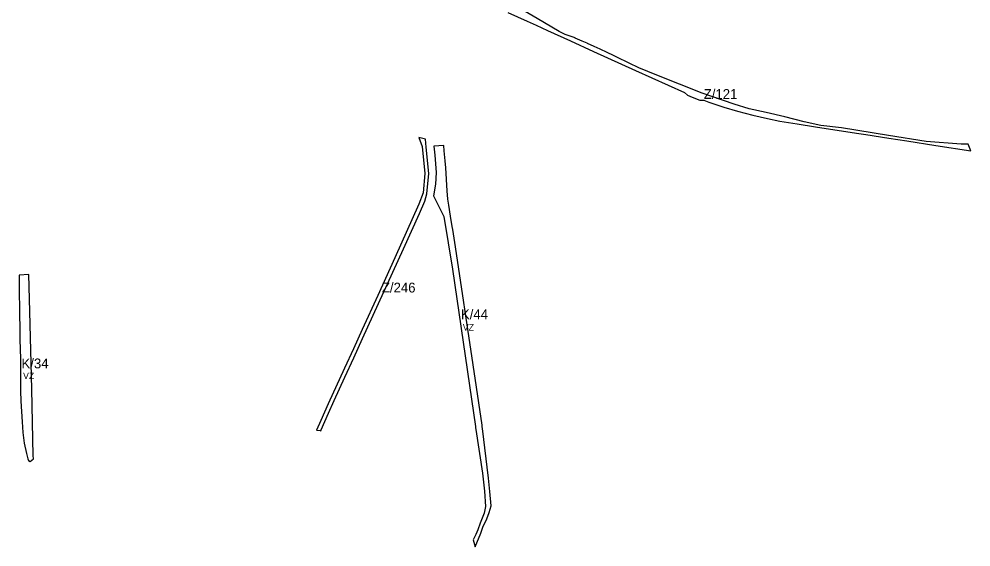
# Model space of a CAD drawing. Extents: x -521939 to -518034, y -1194984 to -1189555.
# Drawn here: x -520595 to -519142, y -1193629 to -1192824 of the extents above; entities that cross this region are included whole.
import ezdxf

# ---------------------------------------------------------------- set-up
doc = ezdxf.new("R2010")
doc.units = 0
for name, color, linetype in [('95420023', 7, 'Continuous'), ('96111023', 7, 'Continuous'), ('96202223', 7, 'Continuous')]:
    doc.layers.add(name, color=color, linetype=linetype)

msp = doc.modelspace()

# ---------------------------------------------------------------- linework, layer by layer
at = {"layer": '95420023'}
for points in [[(-519727.02, -1192861.14), (-519727.74, -1192860.81), (-519735.5, -1192857.45), (-519745.77, -1192853), (-519746.17, -1192852.82), (-519761.29, -1192847.68), (-519770.17, -1192843), (-519803.79, -1192823.02), (-519842.92, -1192800.19)], [(-519848.77, -1192813.79), (-519819.07, -1192827.26)], [(-519819.07, -1192827.26), (-519805.68, -1192833.36)], [(-519805.68, -1192833.36), (-519788.21, -1192841.3)], [(-519788.21, -1192841.3), (-519752.94, -1192857.37)], [(-519752.94, -1192857.37), (-519717.76, -1192873.41)], [(-519717.04, -1192865.69), (-519727.02, -1192861.14)], [(-519717.76, -1192873.41), (-519653.99, -1192902.46)], [(-519707.74, -1192869.98), (-519717.04, -1192865.69)], [(-519677.43, -1192884.57), (-519687.55, -1192879.63), (-519697.18, -1192875), (-519707.74, -1192869.98)], [(-519657.29, -1192894.4), (-519668.57, -1192888.89), (-519677.43, -1192884.57)], [(-519648.88, -1192898.4), (-519655.13, -1192895.45), (-519657.29, -1192894.4)], [(-519653.99, -1192902.46), (-519579.08, -1192936.23)], [(-519621.37, -1192909.57), (-519648.88, -1192898.4)], [(-519551.94, -1192937.22), (-519621.37, -1192909.57)], [(-519579.08, -1192936.23), (-519574.51, -1192940.18), (-519567.2, -1192943.06)], [(-519503.57, -1192953.95), (-519551.94, -1192937.22)], [(-519567.2, -1192943.06), (-519555.74, -1192947.57), (-519549.76, -1192947.78), (-519542.07, -1192950.61)], [(-519542.07, -1192950.61), (-519518.93, -1192958.37)], [(-519518.93, -1192958.37), (-519498.2, -1192964.55)], [(-519480.63, -1192960.73), (-519503.57, -1192953.95)], [(-519498.2, -1192964.55), (-519474.87, -1192970.68)], [(-519425.99, -1192972.98), (-519454.77, -1192966.51), (-519480.63, -1192960.73)], [(-519474.87, -1192970.68), (-519452.37, -1192975.76)], [(-519452.37, -1192975.76), (-519433.72, -1192979.51)], [(-519433.72, -1192979.51), (-519407.22, -1192983.93)], [(-519370.98, -1192986.14), (-519396.52, -1192980.8), (-519425.99, -1192972.98)], [(-519407.22, -1192983.93), (-519379.4, -1192988.21)], [(-519379.4, -1192988.21), (-519316.79, -1192997.86)], [(-519339.75, -1192990.06), (-519370.98, -1192986.14)], [(-519157.21, -1193014.6), (-519210.29, -1193010.83), (-519267.67, -1193001.68), (-519339.75, -1192990.06)], [(-519974.42, -1193007.26), (-519984.44, -1193004.38)], [(-519984.44, -1193004.38), (-519979.35, -1193018.09)], [(-519973.19, -1193019.52), (-519974.42, -1193007.26)], [(-519316.79, -1192997.86), (-519302.57, -1193000.06)], [(-519302.57, -1193000.06), (-519267.23, -1193005.51)], [(-519267.23, -1193005.51), (-519239.74, -1193009.74)], [(-519239.74, -1193009.74), (-519195.48, -1193016.56)], [(-519979.35, -1193018.09), (-519975.45, -1193059.33)], [(-519969.42, -1193059.31), (-519973.19, -1193019.52)], [(-519195.48, -1193016.56), (-519142.04, -1193024.85)], [(-519146.2, -1193014.77), (-519157.21, -1193014.6)], [(-519142.04, -1193024.85), (-519146.2, -1193014.77)], [(-519975.45, -1193059.33), (-519978.09, -1193089.18)], [(-519972.17, -1193090.33), (-519969.42, -1193059.31)], [(-520008.16, -1193174.24), (-519983.64, -1193120.33), (-519975.56, -1193101.44), (-519972.17, -1193090.33)], [(-519978.09, -1193089.18), (-519984.32, -1193106.32)], [(-519984.32, -1193106.32), (-520021.04, -1193188.07)], [(-520070.47, -1193311.24), (-520008.16, -1193174.24)], [(-520021.04, -1193188.07), (-520047.22, -1193245.62)], [(-520047.22, -1193245.62), (-520070.77, -1193297.42)], [(-520070.77, -1193297.42), (-520084.24, -1193326.9)], [(-520083.91, -1193340.59), (-520070.47, -1193311.24)], [(-520084.24, -1193326.9), (-520097.84, -1193356.45)], [(-520097.51, -1193370.06), (-520083.91, -1193340.59)], [(-520097.84, -1193356.45), (-520122.68, -1193410.82)], [(-520122.34, -1193424.94), (-520113.77, -1193405.48), (-520097.51, -1193370.06)], [(-520122.68, -1193410.82), (-520133.9, -1193436.21)], [(-520134.2, -1193451.67), (-520133.56, -1193450.26), (-520122.34, -1193424.94)], [(-520133.9, -1193436.21), (-520140.41, -1193450.83)], [(-520140.41, -1193450.83), (-520134.88, -1193451.49)], [(-520134.88, -1193451.49), (-520134.2, -1193451.67)]]:
    msp.add_lwpolyline(points, dxfattribs=at)
at = {"layer": '96111023'}
for points in [[(-519946.52, -1193016.85), (-519961.59, -1193017.82)], [(-519961.59, -1193017.82), (-519959.95, -1193031.63), (-519957.98, -1193057.97)], [(-519945.63, -1193024.86), (-519946.52, -1193016.85)], [(-519944.11, -1193039.95), (-519945.63, -1193024.86)], [(-519943.25, -1193050.97), (-519944.11, -1193039.95)], [(-519940.04, -1193098.62), (-519941.21, -1193085.76), (-519943.25, -1193050.97)], [(-519957.98, -1193057.97), (-519959.22, -1193075.94)], [(-519959.22, -1193075.94), (-519962.06, -1193093.75)], [(-519962.06, -1193093.75), (-519946.35, -1193125.19), (-519933.38, -1193205.21), (-519907.35, -1193382.83), (-519898.22, -1193445.13)], [(-519938.56, -1193107.97), (-519940.04, -1193098.62)], [(-519936.08, -1193124.31), (-519938.56, -1193107.97)], [(-519933.44, -1193140.29), (-519936.08, -1193124.31)], [(-519932.83, -1193144.89), (-519933.44, -1193140.29)], [(-519928.77, -1193171.13), (-519932.83, -1193144.89)], [(-519887.86, -1193443.3), (-519901.66, -1193351.49), (-519928.77, -1193171.13)], [(-520579.39, -1193213.66), (-520594.54, -1193214.33)], [(-520578.05, -1193270.09), (-520579.39, -1193213.66)], [(-520594.54, -1193214.33), (-520594.36, -1193228.5)], [(-520594.36, -1193228.5), (-520594.2, -1193241.7)], [(-520594.2, -1193241.7), (-520593.91, -1193264.71)], [(-520593.91, -1193264.71), (-520593.84, -1193270.47)], [(-520593.84, -1193270.47), (-520593.48, -1193299.21)], [(-520572.81, -1193489.53), (-520575.23, -1193388.1), (-520578.05, -1193270.09)], [(-520593.48, -1193299.21), (-520593.16, -1193312.67)], [(-520593.16, -1193312.67), (-520592.81, -1193327.52)], [(-520592.81, -1193327.52), (-520592.34, -1193342.18)], [(-520592.34, -1193342.18), (-520592.11, -1193358.68)], [(-520592.11, -1193358.68), (-520592.07, -1193374.76)], [(-520592.07, -1193374.76), (-520592.13, -1193390.79)], [(-520592.13, -1193390.79), (-520591.63, -1193406.88)], [(-520591.63, -1193406.88), (-520590.94, -1193422.65)], [(-520590.94, -1193422.65), (-520590.74, -1193422.65), (-520589.86, -1193438.24)], [(-520589.86, -1193438.24), (-520588.57, -1193454.26)], [(-519897.8, -1193447.56), (-519897.38, -1193449.99), (-519887.36, -1193516.57), (-519884.47, -1193543.82), (-519882.69, -1193567.19), (-519884.76, -1193577.59), (-519890.7, -1193592.62), (-519894.55, -1193602.68), (-519897.73, -1193609.81), (-519901.37, -1193618.32), (-519898.76, -1193628.94), (-519889.94, -1193607.87), (-519886.16, -1193597.43), (-519883.14, -1193591.58), (-519880.89, -1193586.23), (-519877.16, -1193576.19), (-519873.92, -1193566.11), (-519876.28, -1193544.38), (-519878.23, -1193524.18), (-519887.53, -1193448.24), (-519887.69, -1193445.77)], [(-519898.22, -1193445.13), (-519897.8, -1193447.56)], [(-519887.69, -1193445.77), (-519887.86, -1193443.3)], [(-520588.57, -1193454.26), (-520586.93, -1193470.68)], [(-520586.93, -1193470.68), (-520583.19, -1193486.29)], [(-520583.19, -1193486.29), (-520581, -1193494.61)], [(-520572.69, -1193494.62), (-520572.81, -1193489.53)], [(-520581, -1193494.61), (-520580.28, -1193497.37)], [(-520580.28, -1193497.37), (-520577.34, -1193498.47)], [(-520577.34, -1193498.47), (-520572.69, -1193494.62)]]:
    msp.add_lwpolyline(points, dxfattribs=at)
at = {"layer": '96202223'}
for points in [[(-519946.52, -1193016.85), (-519961.59, -1193017.82)], [(-519961.59, -1193017.82), (-519959.95, -1193031.63), (-519957.98, -1193057.97)], [(-519945.63, -1193024.86), (-519946.52, -1193016.85)], [(-519944.11, -1193039.95), (-519945.63, -1193024.86)], [(-519943.25, -1193050.97), (-519944.11, -1193039.95)], [(-519940.04, -1193098.62), (-519941.21, -1193085.76), (-519943.25, -1193050.97)], [(-519957.98, -1193057.97), (-519959.22, -1193075.94)], [(-519959.22, -1193075.94), (-519962.06, -1193093.75)], [(-519962.06, -1193093.75), (-519946.35, -1193125.19), (-519933.38, -1193205.21), (-519907.35, -1193382.83), (-519898.22, -1193445.13)], [(-519938.56, -1193107.97), (-519940.04, -1193098.62)], [(-519936.08, -1193124.31), (-519938.56, -1193107.97)], [(-519933.44, -1193140.29), (-519936.08, -1193124.31)], [(-519932.83, -1193144.89), (-519933.44, -1193140.29)], [(-519928.77, -1193171.13), (-519932.83, -1193144.89)], [(-519887.86, -1193443.3), (-519901.66, -1193351.49), (-519928.77, -1193171.13)], [(-520579.39, -1193213.66), (-520594.54, -1193214.33)], [(-520578.05, -1193270.09), (-520579.39, -1193213.66)], [(-520594.54, -1193214.33), (-520594.36, -1193228.5)], [(-520594.36, -1193228.5), (-520594.2, -1193241.7)], [(-520594.2, -1193241.7), (-520593.91, -1193264.71)], [(-520593.91, -1193264.71), (-520593.84, -1193270.47)], [(-520593.84, -1193270.47), (-520593.48, -1193299.21)], [(-520572.81, -1193489.53), (-520575.23, -1193388.1), (-520578.05, -1193270.09)], [(-520593.48, -1193299.21), (-520593.16, -1193312.67)], [(-520593.16, -1193312.67), (-520592.81, -1193327.52)], [(-520592.81, -1193327.52), (-520592.34, -1193342.18)], [(-520592.34, -1193342.18), (-520592.11, -1193358.68)], [(-520592.11, -1193358.68), (-520592.07, -1193374.76)], [(-520592.07, -1193374.76), (-520592.13, -1193390.79)], [(-520592.13, -1193390.79), (-520591.63, -1193406.88)], [(-520591.63, -1193406.88), (-520590.94, -1193422.65)], [(-520590.94, -1193422.65), (-520590.74, -1193422.65), (-520589.86, -1193438.24)], [(-520589.86, -1193438.24), (-520588.57, -1193454.26)], [(-519897.8, -1193447.56), (-519897.38, -1193449.99), (-519887.36, -1193516.57), (-519884.47, -1193543.82), (-519882.69, -1193567.19), (-519884.76, -1193577.59), (-519890.7, -1193592.62), (-519894.55, -1193602.68), (-519897.73, -1193609.81), (-519901.37, -1193618.32), (-519898.76, -1193628.94), (-519889.94, -1193607.87), (-519886.16, -1193597.43), (-519883.14, -1193591.58), (-519880.89, -1193586.23), (-519877.16, -1193576.19), (-519873.92, -1193566.11), (-519876.28, -1193544.38), (-519878.23, -1193524.18), (-519887.53, -1193448.24), (-519887.69, -1193445.77)], [(-519898.22, -1193445.13), (-519897.8, -1193447.56)], [(-519887.69, -1193445.77), (-519887.86, -1193443.3)], [(-520588.57, -1193454.26), (-520586.93, -1193470.68)], [(-520586.93, -1193470.68), (-520583.19, -1193486.29)], [(-520583.19, -1193486.29), (-520581, -1193494.61)], [(-520572.69, -1193494.62), (-520572.81, -1193489.53)], [(-520581, -1193494.61), (-520580.28, -1193497.37)], [(-520580.28, -1193497.37), (-520577.34, -1193498.47)], [(-520577.34, -1193498.47), (-520572.69, -1193494.62)]]:
    msp.add_lwpolyline(points, dxfattribs=at)

# ---------------------------------------------------------------- texts
at = {"layer": '95420023'}
for s, rotation, p in [('Z/121', 0, (-519549.73, -1192945.77)), ('Z/246', 360, (-520040.88, -1193240.93))]:
    msp.add_text(s, height=15, rotation=rotation, dxfattribs=at).set_placement(p)
at = {"layer": '96111023'}
for s, p in [('K/44', (-519920.22, -1193281.8)), ('K/34', (-520590.74, -1193356.64))]:
    msp.add_text(s, height=15, rotation=360, dxfattribs=at).set_placement(p)
at = {"layer": '96202223'}
for rotation, p in [(360, (-519917.42, -1193299.05)), (0, (-520588.39, -1193372.94))]:
    msp.add_text('VZ', height=10, rotation=rotation, dxfattribs=at).set_placement(p)

doc.saveas('drawing.dxf')
